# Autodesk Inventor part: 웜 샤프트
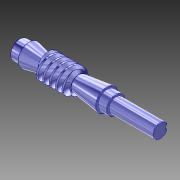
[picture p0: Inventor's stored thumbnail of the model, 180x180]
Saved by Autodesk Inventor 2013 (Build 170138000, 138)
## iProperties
Created: 2013-01
Part Number: 웜 샤프트
Material: 탄소강
Document SubType Name: Modeling
Designer: 한국산업디자인학원[gmhk.co.kr]
Categories: <?xml version="1.0" encoding="UTF-16"?> <MemberInstance><Categories><FamilyTemplate><FamilyTemplateParameter ValueType="xs:double" Id="1" ObjectReferenceKey="da
Density: 7.87 g/cm^3
Mass: 4106.37 g
Surface Area: 646.884 cm^2
Volume: 521.775 cm^3
CustomPartVersion: 1
Author: 한국산업디자인학원[gmhk.co.kr]
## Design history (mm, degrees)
body "Solid1"
extrude "기본 본체" new body stored distance "d6" = 80 (= da_b); taper "d7" = 0 deg
chamfer "Chamfer1" distance "d8" = 4.00367 (= fd_cham1); stored, may be unused: second distance "d9" = 11 (= 0.5 x fd_cham2), angle "d47" = 45 deg
chamfer "Chamfer2" distance "d10" = 4.00367 (= fd_cham1); stored, may be unused: second distance "d11" = 11 (= 0.5 x fd_cham2), angle "d48" = 45 deg
sketch "톱니 스케치"
  geometry: L1 (0, 21.74)-(0, 10.96) reference; L2 (-60.834, 30.3)-(-56.721, 19); L3 (-53.235, 19)-(-49.122, 30.3); L4 (-50.535, 0)-(-37.455, 0) reference; L5 (-60.834, 30.3)-(-54.978, 30.3); L6 (-54.978, 30.3)-(-49.122, 30.3); L7 (-56.721, 19)-(-54.978, 19); L8 (-54.978, 19)-(-53.235, 19); L9 (-54.978, 25)-(-51.051, 25); L10 (-54.978, 30.3)-(-54.978, 19)
  constraints: 16 end point, 3 equal length, 3 parallel, 2 collinear, 2 point on line
  dimensions: "d24" = 110 deg angle of L7 L2 (computed from da_alfat); "d25" = 54.97787 distance from line of L1 L5.end (= fd_dist); "d26" = 3.92699 distance of L9.start L9.end (= 0.25 x da_px); "d27" = 19 distance between parallel lines of L4 L7 (= 0.5 x da_df); "d28" = 25 distance between parallel lines of L4 L9 (= 0.5 x da_d); "d29" = 30.3 distance between parallel lines of L4 L5 (= 0.505 x da_da)
feature "톱니" pitch "d30" = 31.41593 (computed from da_px, da_z); turns "d32" = 8 (= fd_n); dims "d31" = 10, "d33" = 0, angle "d34" = 90 deg, angle "d35" = 90 deg, "d36" = 0, "d37" = 0, "d70" = 10, "da_rightdir" = 0 [user parameter]
pattern_circular "톱니 패턴" dims angle "d46" = 360 deg, "da_rightdir" = 0 [user parameter]
feature "왼쪽 톱니" pitch "d62" = 31.41593 (computed from da_px, da_z); turns "d64" = 8 (= fd_n); dims "d63" = 10, "d65" = 0, angle "d66" = 90 deg, angle "d67" = 90 deg, "d68" = 0, "d69" = 0, "d76" = 10, "da_rightdir" = 0 [user parameter]
pattern_circular "왼쪽 톱니 패턴" dims angle "d73" = 360 deg, "da_rightdir" = 0 [user parameter]
sketch "스케치8"
  geometry: C1 r 18.99 at (0, 0); A1 r 19 centre (0, 0) between (9.02, 16.723) and (-3.823, 18.611) reference; A2 r 19 centre (0, 0) between (-3.823, 18.611) and (-9.02, -16.723) reference; A3 r 19 centre (0, 0) between (-9.02, -16.723) and (3.823, -18.611) reference; A4 r 19 centre (0, 0) between (3.823, -18.611) and (9.02, 16.723) reference; 1 further point
  constraints: 1 centre point, 1 coincident
  dimensions: "d87" = 0.01 radial gap between concentric circles of C1 A2
node "작업 평면10"
extrude "돌출2" join sketch "스케치8" distance "d88" = 1; taper "d89" = 0 deg
mirror "대칭1"
revolve "회전1" stored, may be unused: angle "d90" = 90 deg
chamfer "모따기3" distance "d91" = 1; stored, may be unused: second distance "d92" = 2, angle "d93" = 45 deg
node "작업 평면11"
sketch "스케치9"
  geometry: L1 (-54.5, -16.5)-(-54.5, 16.5) reference; L2 (-54.5, 5)-(-23.5, 5); L3 (-23.5, -5)-(-54.5, -5); A1 r 5 centre (-23.5, 0) between (-23.5, -5) and (-23.5, 5); 2 further points
  constraints: 4 end point, 2 perpendicular, 2 point on circle, 2 point on line, 2 tangent, 1 centre point, 1 horizontal alignment, 1 midpoint
  dimensions: "d94" = 10 distance between parallel lines of L3 L2; "d96" = 36 dimension on A1 L1
extrude "돌출3" cut sketch "스케치9" distance "d97" = 5; taper "d98" = 0 deg
node "기본 본체 스케치" dims "d5" = 60 (= da_da)
sketch "Sketch5"
  geometry: C1 r 30 at (0, 0) reference; C2 r 25 at (0, 0)
  constraints: 1 centre point, 1 coincident
  dimensions: "d59" = 50 diameter of C2 (= da_d)
body "Srf1"
sketch "스케치7"
  geometry: L1 (40, 18.611)-(40, -16.723) reference; L2 (40, 19)-(40, 16.723) reference; L3 (40, 18.611)-(40, 16.723) reference; L4 (40, -16.723)-(40, 18.611) reference; L5 (40, -18.611)-(40, -16.723) reference; L6 (40, 16.723)-(40, -18.611) reference; L7 (40, -16.723)-(40, -19) reference; L8 (41, 0)-(241, 0); L9 (110, 27.5)-(110, 22.5); L10 (110, 22.5)-(132, 22.5); L11 (132, 22.5)-(132, 17.5); L12 (132, 17.5)-(241, 17.5); L13 (241, 17.5)-(241, 0); L14 (127.9, 22.5)-(111.1, 22.5) reference; L15 (110, -41.4)-(110, 41.4) reference; L16 (-40, -16.723)-(-40, 18.611) reference; L17 (-41, 0)-(-105, 0); L18 (25.305, 19)-(-40, 19) reference; L19 (-82, 27.5)-(-82, 22.5); L20 (-82, 22.5)-(-105, 22.5); L21 (-105, 22.5)-(-105, 0); L22 (-82, 41.4)-(-82, -41.4) reference; L23 (41, 18.99)-(41, -18.99) reference; L24 (41, 0)-(41, 18.99); L25 (41, 18.99)-(110, 27.5); L26 (-41, 18.99)-(-41, -18.99) reference; L27 (-41, 0)-(-41, 18.99); L28 (-41, 18.99)-(-82, 27.5); 1 further point
  constraints: 30 end point, 7 collinear, 7 perpendicular, 2 midpoint, 1 horizontal, 1 horizontal alignment, 1 parallel, 1 point on line, 2 other
  dimensions: "d82" = 35 diameter of L12 L8; "d83" = 55 diameter of L9.start L8; "d84" = 22 distance of L9.end L10.end; "d85" = 200 distance of L8.start L8.end; "d86" = 64 distance of L17.start L17.end
node "투영된 루프1"
node "참조1"
node "참조2"
node "투영된 루프2"
feature "피치 지름" dims "d60" = 10, "d61" = 0
other parameters: "da_b" = 80 [user parameter; used in 3 equation terms], "da_df" = 38 [user parameter; used in 2 equation terms], "fd_cham2" = 22 (= da_da - da_df) [user parameter; used in 3 equation terms], "fd_cham1" = 4.00367 (= 0.181985 x fd_cham2) [user parameter; used in 2 equation terms], "da_d" = 50 [user parameter; used in 2 equation terms], "da_px" = 90 deg [user parameter; used in 5 equation terms], "fd_dist" = 54.97787 (computed from da_b, da_px) [user parameter; used in 1 equation term], "fd_n" = 8 (computed from da_b, da_px) [user parameter; used in 2 equation terms], "da_alfat" = 20 deg [user parameter; used in 1 equation term], "d12" = 110 deg (derived), "d14" = 3.1425 (derived), "d50" = 0, "d54" = 0, "d56" = 0, "d77" = 0, "d80" = 0
